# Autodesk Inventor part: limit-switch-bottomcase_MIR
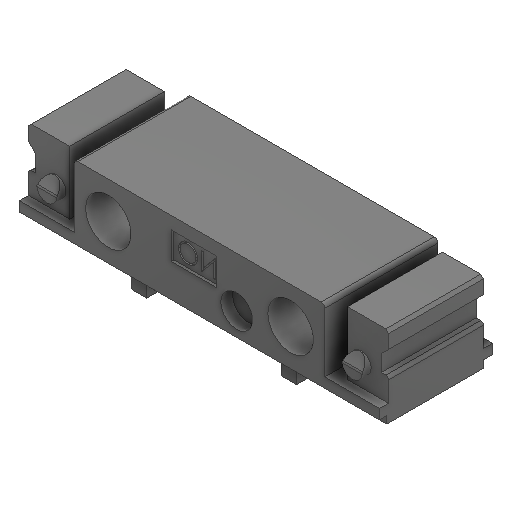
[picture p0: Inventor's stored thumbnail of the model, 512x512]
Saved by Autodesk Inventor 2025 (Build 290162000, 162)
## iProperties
Created: 2025-10
Part Number: limit-switch-bottomcase_MIR
Material: Generico
Document SubType Name: Modeling
Designer: Ryzen5700u
Density: 1 g/cm^3
Appearance: Default
Author: Ryzen5700u
Revision Number: ANY
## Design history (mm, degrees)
derived "limit-switch-bottomcase.ipt"
feature "Solido1::limit-switch-bottomcase.ipt" dims "d0" = 10
tag "Lavorazione contrassegno1"
node "Solido1"
